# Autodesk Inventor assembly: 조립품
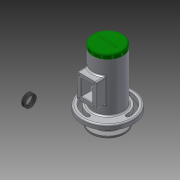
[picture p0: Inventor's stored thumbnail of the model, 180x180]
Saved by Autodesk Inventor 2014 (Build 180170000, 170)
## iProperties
Created: 2017-05
Part Number: 조립품
Document SubType Name: Assembly
Designer: Administrator
Author: Administrator
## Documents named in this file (17)
- C:\Users\Administrator\Desktop\470507V1005\조립품.iam
- C:\Users\Administrator\Desktop\470507V1005\본체.ipt
- C:\Users\Administrator\Desktop\470507V1005\축.ipt
- C:\Users\Administrator\Desktop\470507V1005\베어링 15 x 35 x 11.ipt
- C:\Users\Administrator\Desktop\470507V1005\부시1.ipt
- C:\Users\Administrator\Desktop\470507V1005\멈춤링 35x1.6.ipt
- C:\Users\Administrator\Desktop\470507V1005\멈춤링 15 x 1.ipt
- C:\Users\Administrator\Desktop\470507V1005\부시2.ipt
- C:\Users\Administrator\Desktop\470507V1005\와셔 10x21.ipt
- C:\Users\Administrator\Desktop\470507V1005\너트 M10.ipt
- C:\Users\Administrator\Desktop\470507V1005\사이드 커버.ipt
- 사이드 커버.ipt
- C:\Users\Administrator\Desktop\470507V1005\키 4 x 4 x 18.ipt
- C:\Users\Administrator\Desktop\470507V1005\V-벨트풀리.ipt
- C:\Users\Administrator\Desktop\470507V1005\와셔 4x16.ipt
- C:\Users\Administrator\Desktop\470507V1005\볼트 M4 x 10.ipt
- C:\Users\Administrator\Desktop\470507V1005\오일 실 15 25 7.ipt
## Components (2 placed, 2 different names)
1. V-벨트풀리:1
2. ISO 4017 M4 x 10:1
